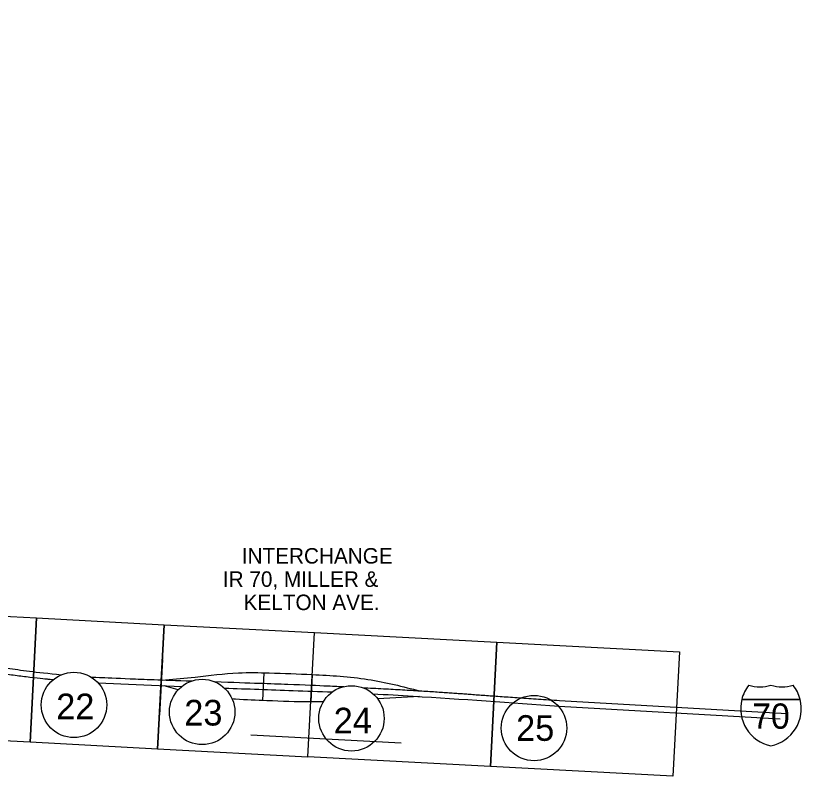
# Model space of a CAD drawing. Extents: x -13 to 322, y -402 to 112.
# Drawn here: x 7.61 to 12.62, y 68.23 to 73.08 of the extents above; entities that cross this region are included whole.
import ezdxf

# ---------------------------------------------------------------- set-up
doc = ezdxf.new("R2010")
doc.units = 0
for name, color, linetype in [('Default', 7, 'Continuous'), ('GM_X_Interstate_Shield', 7, 'Continuous'), ('SC_Scratch1', 7, 'Continuous'), ('SH_Data', 7, 'Continuous'), ('SH_Text', 7, 'Continuous')]:
    doc.layers.add(name, color=color, linetype=linetype)

# ---------------------------------------------------------------- blocks, each defined once
blk = doc.blocks.new('FENCE')
at = {"layer": 'Default'}
blk.add_lwpolyline([(-54.6, 79.5), (232.4, 79.5), (232.4, -116), (-54.6, -116)], close=True, dxfattribs=at)

msp = doc.modelspace()

# ---------------------------------------------------------------- linework, layer by layer
at = {"layer": 'GM_X_Interstate_Shield'}
for p, q in [((12.2403, 68.7255), (12.6123, 68.7255)), ((12.6123, 68.7255), (12.2403, 68.7255)), ((12.6123, 68.7255), (12.2403, 68.7255))]:
    msp.add_line(p, q, dxfattribs=at)
for centre, start, end in [((12.4747, 68.6662), 141.669, 165.8066), ((12.3557, 69.0473), 253.0091, 286.9909), ((12.497, 69.0473), 253.0091, 286.9909), ((12.378, 68.6662), 14.1934, 38.331), ((12.4747, 68.6662), 165.8066, 258.463), ((12.378, 68.6662), 281.537, 14.1934)]:
    msp.add_arc(centre, 0.2417, start, end, dxfattribs=at)
at = {"layer": 'SC_Scratch1'}
for p, q in [((7.7027, 68.4514), (7.7446, 69.2444)), ((7.7446, 69.2444), (7.7027, 68.4514)), ((7.7027, 68.4514), (7.7446, 69.2444)), ((7.7446, 69.2444), (8.5577, 69.2015)), ((8.5158, 68.4084), (8.5577, 69.2015)), ((8.5577, 69.2015), (8.5158, 68.4084)), ((8.5577, 69.2015), (9.5156, 69.1509)), ((7.7337, 69.0394), (7.7171, 68.7256)), ((8.5461, 68.9806), (8.5272, 68.6243)), ((9.1111, 68.4984), (10.0691, 68.4478)), ((8.5158, 68.4084), (7.7027, 68.4514)), ((9.4737, 68.3578), (8.5158, 68.4084))]:
    msp.add_line(p, q, dxfattribs=at)
at = {"layer": 'SH_Data'}
for p, q in [((9.1937, 68.8952), (9.1852, 68.7176)), ((9.1937, 68.8952), (9.1852, 68.7176)), ((9.5015, 68.8838), (9.4923, 68.7088)), ((9.5015, 68.8838), (9.4923, 68.7088)), ((8.1366, 68.8305), (8.6701, 68.808)), ((8.6475, 68.787), (8.5569, 68.8123)), ((10.1854, 68.7433), (9.9192, 68.7284)), ((11.0781, 68.7182), (12.5274, 68.6342)), ((11.0758, 68.683), (12.4843, 68.6004))]:
    msp.add_line(p, q, dxfattribs=at)
for points in [[(4.9981, 72.2459), (5.1483, 72.2055), (5.2518, 72.1811), (5.4323, 72.1404), (5.5235, 72.1195), (5.6034, 72.1121), (5.6861, 72.1153), (5.7355, 72.1253), (5.7778, 72.1357), (5.8594, 72.1765), (5.8968, 72.2042), (5.9464, 72.2456), (5.9929, 72.2989), (6.0481, 72.3994), (6.0943, 72.525), (6.1109, 72.6421), (6.1254, 72.809), (6.1376, 72.8857), (6.1702, 73.0026), (6.211, 73.0952), (6.2763, 73.1933), (6.3428, 73.2685), (6.3653, 73.2857), (6.4612, 73.3619), (6.542, 73.4064), (6.6444, 73.4447), (6.7391, 73.4623), (6.8117, 73.4683), (6.9653, 73.4683), (7.0726, 73.4713), (7.2097, 73.4784), (7.357, 73.494), (7.5219, 73.5113), (7.7497, 73.5556)], [(8.5662, 68.8489), (8.7544, 68.8676), (9.0309, 68.8942), (9.2279, 68.8942), (9.5015, 68.8838), (9.8566, 68.853), (10.1892, 68.7789)], [(8.9421, 68.7973), (9.3799, 68.7818), (9.6292, 68.7725)], [(9.5723, 68.7098), (9.4923, 68.7088), (9.2132, 68.7165), (9.0132, 68.7263), (8.9911, 68.7278)], [(9.889, 68.761), (10.1448, 68.7461), (11.0758, 68.683)]]:
    msp.add_spline(points, degree=3, dxfattribs=at)
for points, degree in [([(7.0452, 68.9938), (7.1606, 68.9807), (7.2757, 68.9657), (7.5619, 68.9243), (7.7318, 68.8991), (7.903, 68.8824)], 3), ([(7.3063, 68.9231), (7.3754, 68.9131), (7.4444, 68.9028), (7.5135, 68.8928), (7.6078, 68.8792), (7.7022, 68.8669), (7.7969, 68.857), (7.815, 68.8551), (7.8331, 68.8533), (7.8512, 68.8515)], 3), ([(8.091, 68.868), (8.1011, 68.8675), (8.1113, 68.867), (8.3259, 68.8572), (8.5305, 68.8499), (8.7352, 68.843)], 3), ([(8.8778, 68.8383), (9.1186, 68.8302), (9.3595, 68.8222), (9.6346, 68.8099), (9.6687, 68.8083), (9.7029, 68.8067)], 3), ([(9.8213, 68.8006), (10.2407, 68.7783), (10.6594, 68.7466), (11.0781, 68.7182)], 2)]:
    msp.add_open_spline(points, degree=degree, dxfattribs=at)
at = {"layer": 'SH_Text'}
for p, q in [((6.9314, 69.2874), (7.7446, 69.2444)), ((7.7446, 69.2444), (7.7027, 68.4514)), ((7.7446, 69.2444), (8.5577, 69.2015)), ((8.5577, 69.2015), (8.5158, 68.4084)), ((8.5577, 69.2015), (9.5156, 69.1509)), ((7.7027, 68.4514), (6.8895, 68.4943)), ((8.5158, 68.4084), (7.7027, 68.4514)), ((9.4737, 68.3578), (8.5158, 68.4084))]:
    msp.add_line(p, q, dxfattribs=at)
for centre in [(7.9828, 68.6899), (8.7999, 68.645), (9.7519, 68.6041), (10.9157, 68.5426)]:
    msp.add_circle(centre, 0.2084, dxfattribs=at)

# ---------------------------------------------------------------- block references
at = {"layer": 'SC_Scratch1', "xscale": 0.00406045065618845, "yscale": 0.004060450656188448, "rotation": 176.97609133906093}
msp.add_blockref('FENCE', (10.433, 68.6306), dxfattribs=at)
at = {"layer": 'SH_Text', "xscale": 0.00406045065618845, "yscale": 0.004060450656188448, "rotation": 176.97609133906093}
for p in [(10.433, 68.6306), (11.5968, 68.5691)]:
    msp.add_blockref('FENCE', p, dxfattribs=at)

# ---------------------------------------------------------------- texts
at = {"layer": 'GM_X_Interstate_Shield'}
msp.add_text('70', height=0.16115, dxfattribs=at).set_placement((12.3065, 68.5381))
at = {"layer": 'SH_Text'}
for s, height, p in [('INTERCHANGE', 0.098862, (9.0527, 69.5911)), ('IR 70, MILLER &', 0.098862, (8.932, 69.4428)), ('KELTON AVE.', 0.098862, (9.0643, 69.2945)), ('22', 0.16356, (7.8695, 68.5986)), ('23', 0.16356, (8.686, 68.5586)), ('24', 0.16356, (9.6386, 68.5083)), ('25', 0.16356, (10.8017, 68.4609))]:
    msp.add_text(s, height=height, dxfattribs=at).set_placement(p)

doc.saveas('drawing.dxf')
